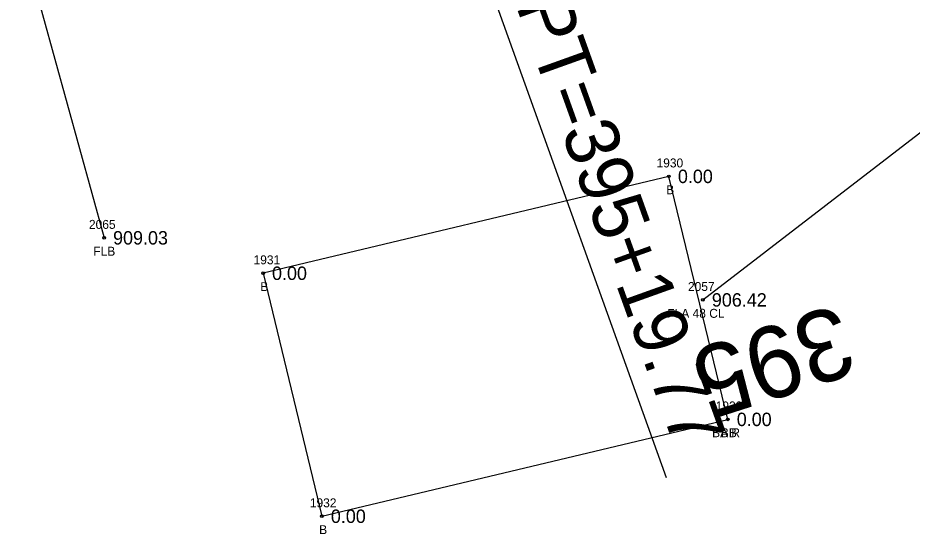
# Model space of a CAD drawing. Extents: x 1448136 to 1453623, y 1125056 to 1128842.
# Drawn here: x 1448899.2 to 1448999.1, y 1126779.2 to 1126836.9 of the extents above; entities that cross this region are included whole.
import ezdxf

# ---------------------------------------------------------------- set-up
doc = ezdxf.new("R2010")
doc.units = 0
for name, color, linetype in [('RD_EX_Bldg', 7, 'Continuous'), ('RD_EX_Bldg_txCode', 7, 'Continuous'), ('RD_EX_Fence_Other', 7, 'Continuous'), ('RD_EX_Fence_Other_txCode', 7, 'Continuous'), ('RD_EX_TX_Bldg_ELEV', 7, 'Continuous'), ('RD_EX_TX_Fence_Other_ELEV', 7, 'Continuous'), ('RD_HC_Data', 7, 'Continuous'), ('RD_HC_TX_Sta50', 7, 'Continuous'), ('RD_SMD_Locator', 7, 'Continuous')]:
    doc.layers.add(name, color=color, linetype=linetype)

msp = doc.modelspace()

# ---------------------------------------------------------------- linework, layer by layer
at = {"layer": 'RD_EX_Bldg'}
msp.add_lwpolyline([(1448978.542, 1126792.038), (1448971.964, 1126819.217), (1448926.599, 1126808.381), (1448933.176, 1126781.203), (1448978.542, 1126792.038)], dxfattribs=at)
at = {"layer": 'RD_EX_Fence_Other'}
msp.add_lwpolyline([(1448975.759, 1126805.398), (1449010.372, 1126832.062), (1449003.734, 1126876.292), (1448947.015, 1126861.168), (1448899.195, 1126847.354), (1448908.832, 1126812.344)], dxfattribs=at)
at = {"layer": 'RD_HC_Data'}
msp.add_line((1448931.001, 1126898.828), (1448971.658, 1126785.537), dxfattribs=at)
at = {"layer": 'RD_SMD_Locator'}
for centre in [(1448971.964, 1126819.217), (1448908.832, 1126812.344), (1448926.599, 1126808.381), (1448975.759, 1126805.398), (1448978.542, 1126792.038), (1448978.542, 1126792.038), (1448933.176, 1126781.203)]:
    msp.add_circle(centre, 0.15, dxfattribs=at)

# ---------------------------------------------------------------- texts
at = {"layer": 'RD_EX_Bldg_txCode'}
for s, p in [('1930', (1448970.578, 1126820.217)), ('B', (1448971.657, 1126817.217)), ('1931', (1448925.536, 1126809.381)), ('B', (1448926.292, 1126806.381)), ('1929', (1448977.195, 1126793.038)), ('1933', (1448977.195, 1126793.038)), ('BA R', (1448976.786, 1126790.038)), ('BB', (1448977.762, 1126790.038)), ('1932', (1448931.829, 1126782.203)), ('B', (1448932.869, 1126779.203))]:
    msp.add_text(s, height=1, dxfattribs=at).set_placement(p)
at = {"layer": 'RD_EX_Fence_Other_txCode'}
for s, p in [('2065', (1448907.139, 1126813.344)), ('FLB', (1448907.627, 1126810.344)), ('2057', (1448974.09, 1126806.398)), ('FLA 48 CL', (1448971.783, 1126803.398))]:
    msp.add_text(s, height=1, dxfattribs=at).set_placement(p)
at = {"layer": 'RD_EX_TX_Bldg_ELEV'}
for p in [(1448972.964, 1126818.467), (1448927.599, 1126807.631), (1448979.542, 1126791.288), (1448979.542, 1126791.288), (1448934.176, 1126780.453)]:
    msp.add_text('0.00', height=1.5, dxfattribs=at).set_placement(p)
at = {"layer": 'RD_EX_TX_Fence_Other_ELEV'}
for s, p in [('909.03', (1448909.832, 1126811.594)), ('906.42', (1448976.759, 1126804.648))]:
    msp.add_text(s, height=1.5, dxfattribs=at).set_placement(p)
at = {"layer": 'RD_HC_Data'}
msp.add_text('PT=395+19.77', height=6, rotation=289.74133, dxfattribs=at).set_placement((1448954.839, 1126838.323))
at = {"layer": 'RD_HC_TX_Sta50'}
msp.add_text('395', height=8, rotation=197.76428, dxfattribs=at).set_placement((1448990.956, 1126804.987))

doc.saveas('drawing.dxf')
